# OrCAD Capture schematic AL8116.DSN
size Custom; title: AL8116-SIGNAL INTERFACE CONTROLLER; rev: 1.1; note: DS42629 Rev. 2 - 2
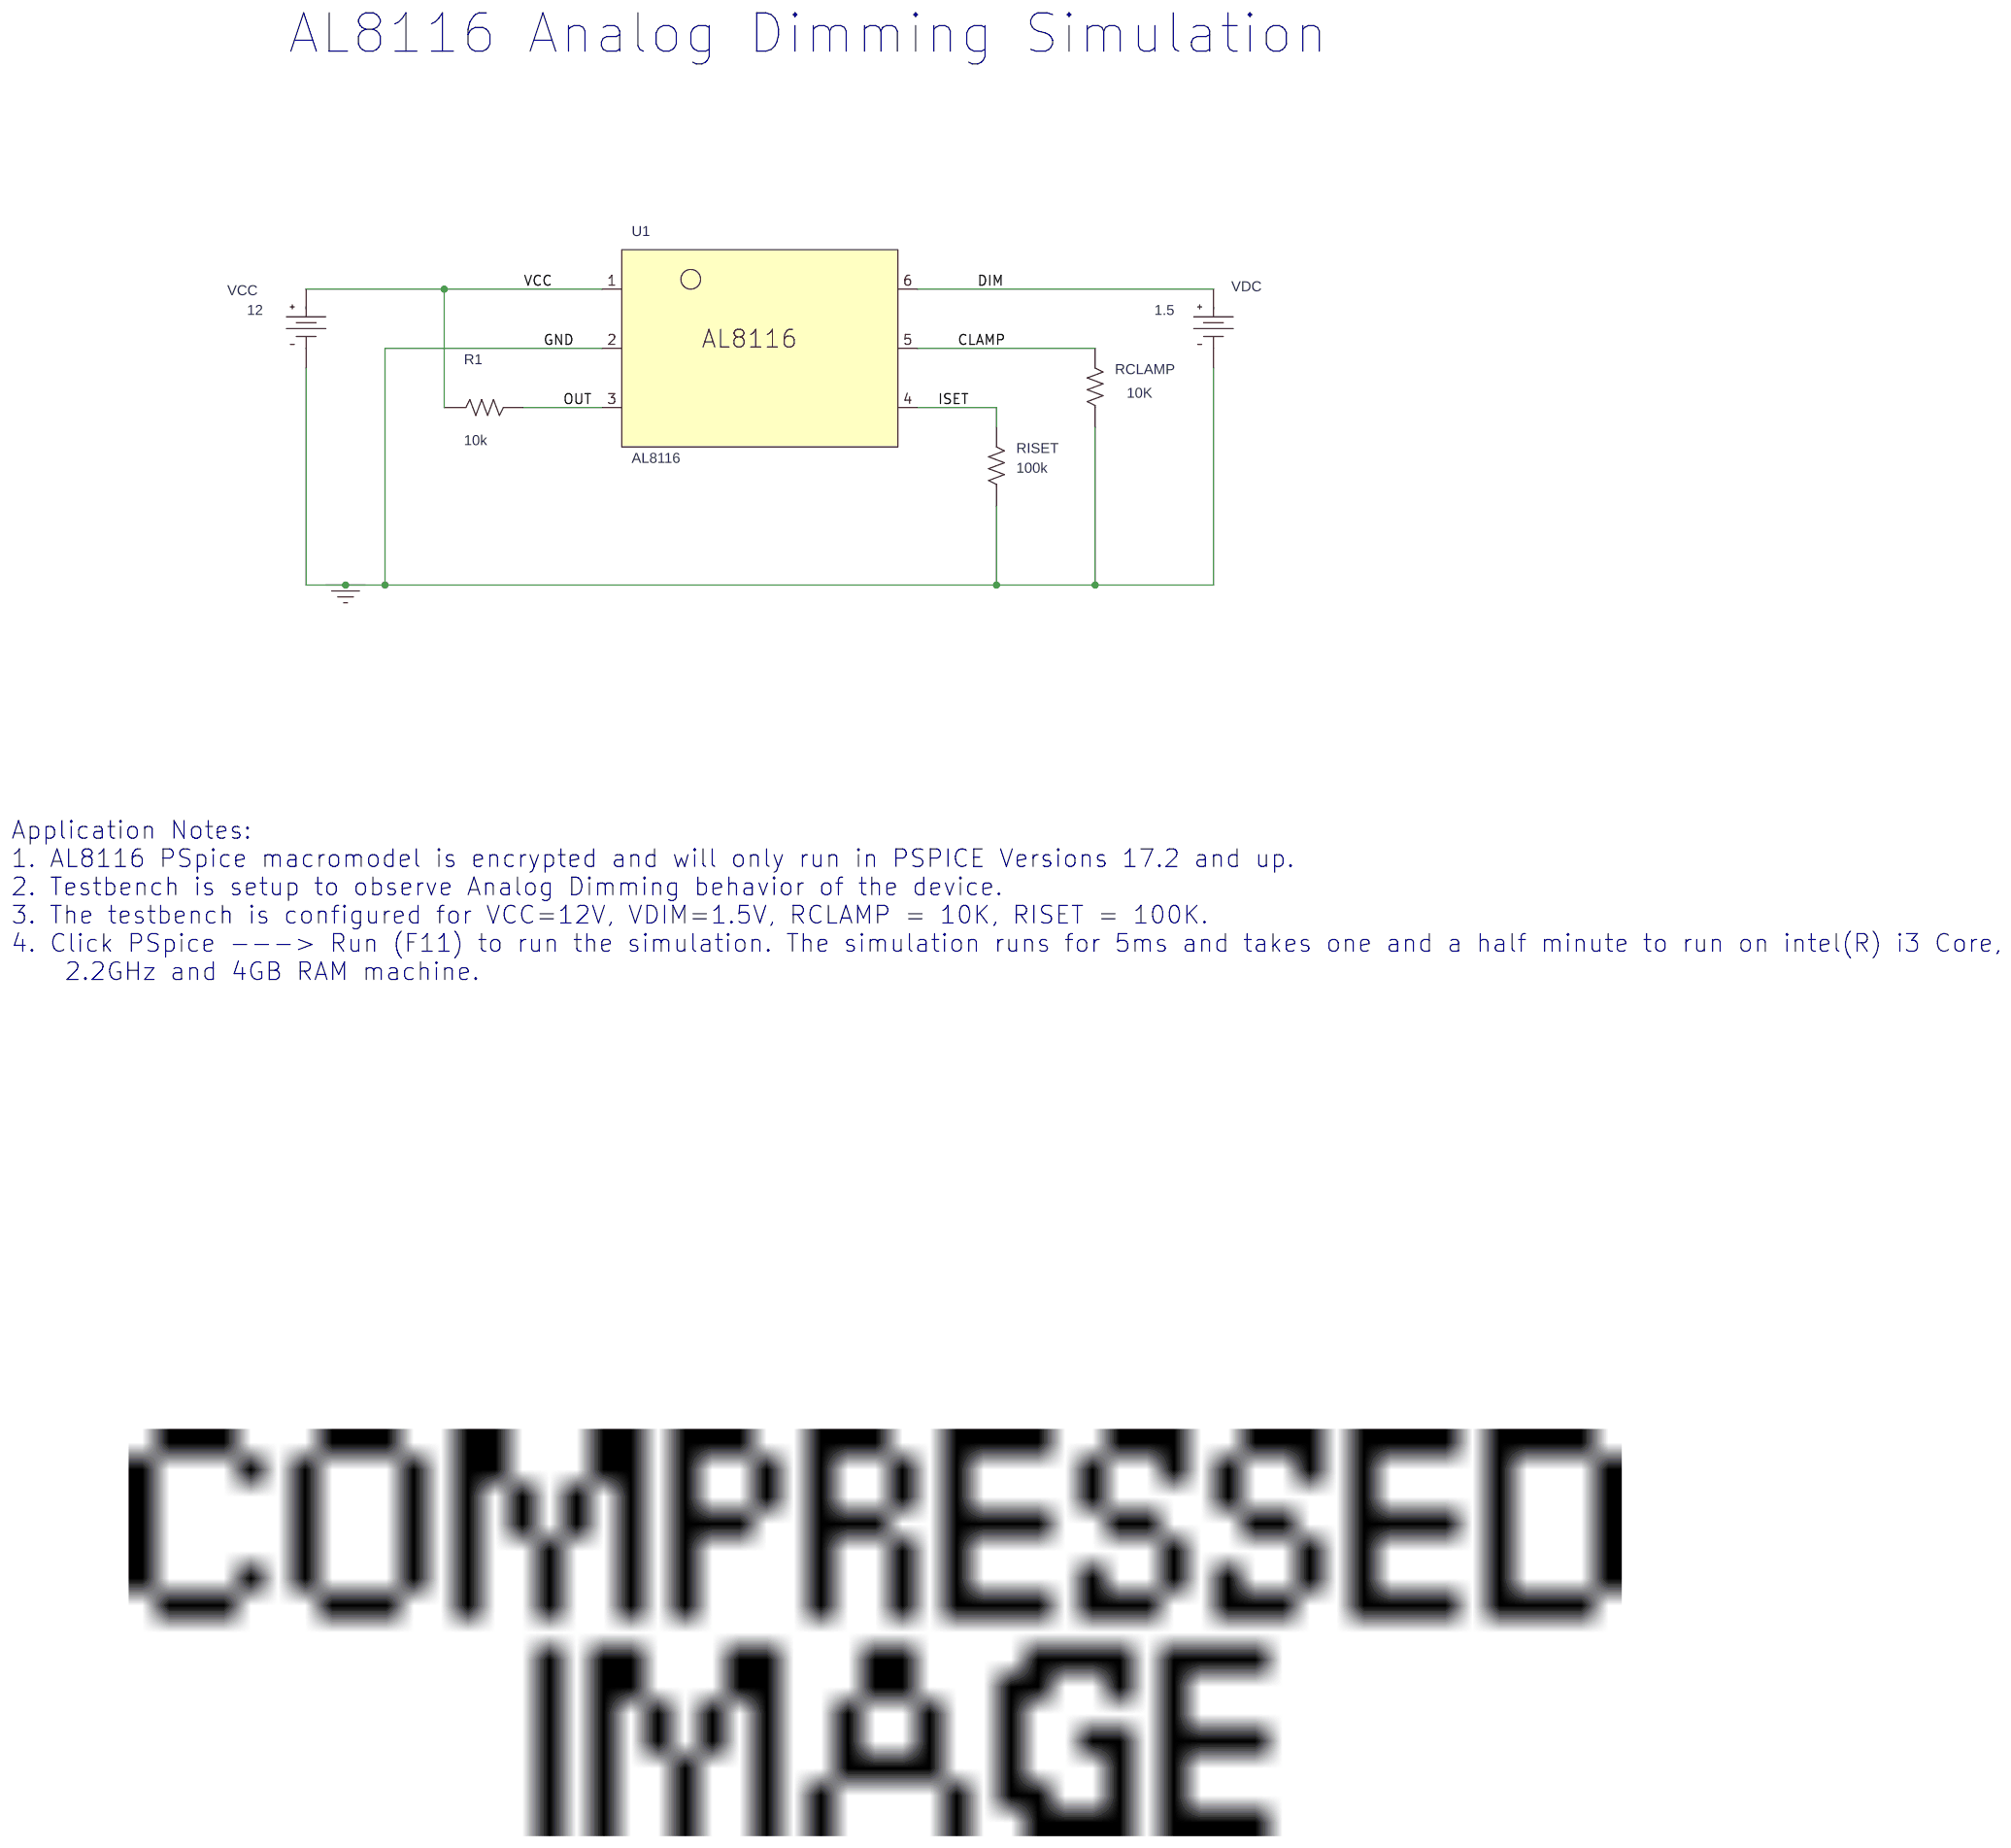
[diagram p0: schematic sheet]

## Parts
R1  10k  [AX/RC05]
RCLAMP  10K  [AX/RC05]
RISET  100k  [AX/RC05]
U1  AL8116
VCC  VDC
VDC  VDC

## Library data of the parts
R1 RCLAMP RISET = r
U1 = AL8116_1
VCC = VDC: DC: 12
VDC = VDC: DC: 1.5

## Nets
VCC: R1.1 U1.1(VCC) VCC.0(+)
0: RCLAMP.1 RISET.1 U1.2(GND) VCC.1(-) VDC.1(-)
CLAMP: RCLAMP.2 U1.5(CLAMP)
DIM: U1.6(DIM) VDC.0(+)
ISET: RISET.2 U1.4(ISET)
OUT: R1.2 U1.3(OUT)

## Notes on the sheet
- AL8116 Analog Dimming Simulation
- Application Notes:
  1. AL8116 PSpice macromodel is encrypted and will only run in PSPICE Versions 17.2 and up.
  2. Testbench is setup to observe Analog Dimming behavior of the device.
  3. The testbench is configured for VCC=12V, VDIM=1.5V, RCLAMP = 10K, RISET = 100K.
  4. Click PSpice ---> Run (F11) to run the simulation. The simulation runs for 5ms and takes one and a half minute to run on intel(R) i3 Core,
      2.2GHz and 4GB RAM machine.
